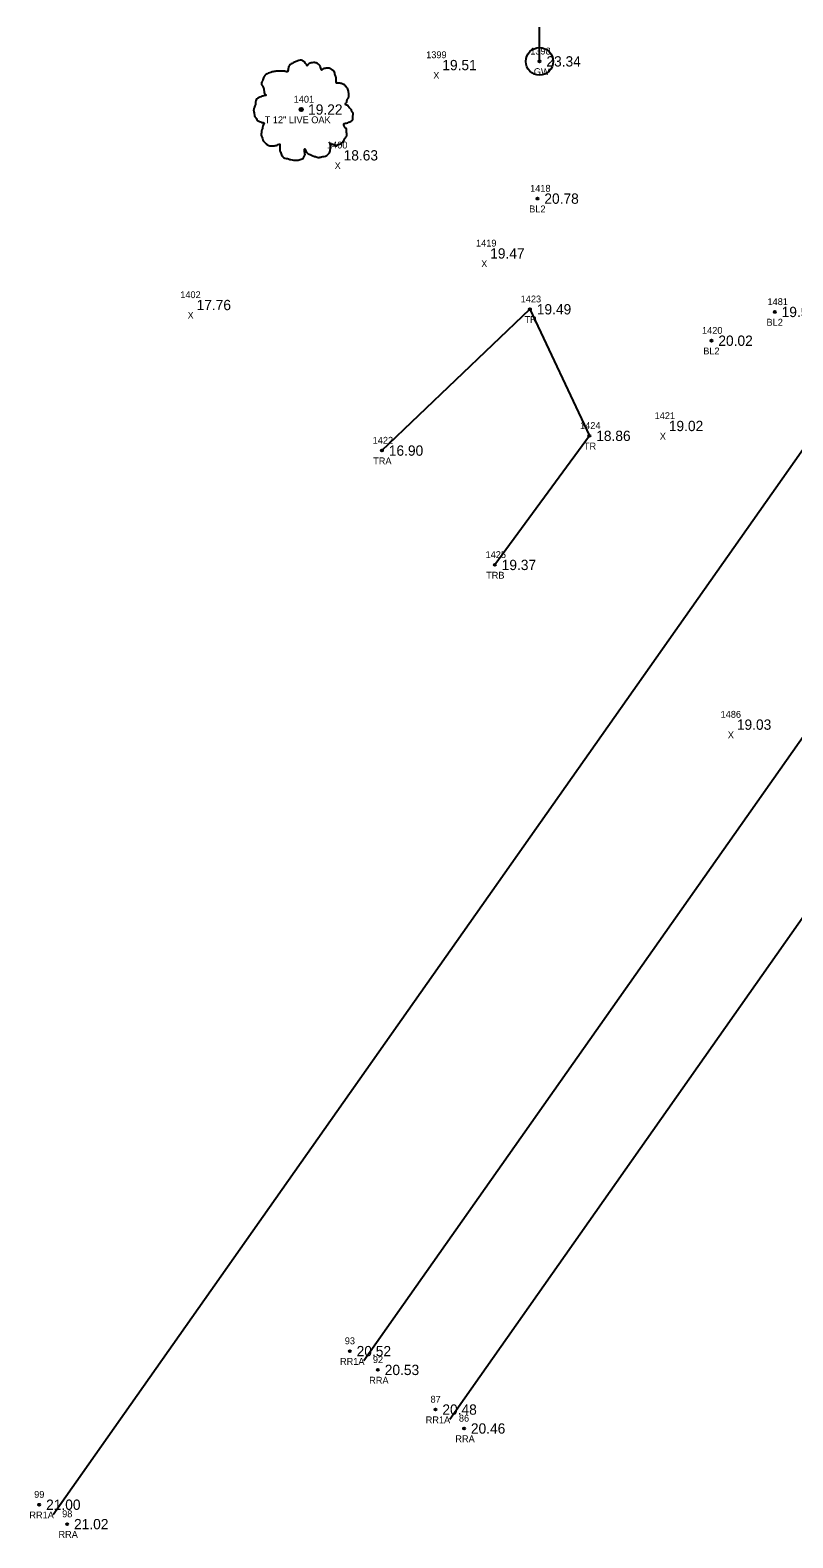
# Model space of a CAD drawing. Extents: x 2042117 to 2045853, y 303080 to 309569.
# Drawn here: x 2043315.7 to 2043426.9, y 305685 to 305904.8 of the extents above; entities that cross this region are included whole.
import ezdxf

# ---------------------------------------------------------------- set-up
doc = ezdxf.new("R2010")
doc.units = 0
for name, color, linetype in [('RD_DTM_BkLn_txCode', 7, 'Continuous'), ('RD_EX_Misc_txCode', 7, 'Continuous'), ('RD_EX_RailRoad', 7, 'Continuous'), ('RD_EX_RailRoad_txCode', 7, 'Continuous'), ('RD_EX_TX_Misc_ELEV', 7, 'Continuous'), ('RD_EX_TX_RailRoad_ELEV', 7, 'Continuous'), ('RD_EX_TX_UT_ELEV', 7, 'Continuous'), ('RD_EX_TX_VEG_ELEV', 7, 'Continuous'), ('RD_EX_UT', 7, 'Continuous'), ('RD_EX_UT_txCode', 7, 'Continuous'), ('RD_EX_VEG', 7, 'Continuous'), ('RD_EX_VEG_txCode', 7, 'Continuous'), ('RD_SMD_Locator', 7, 'Continuous')]:
    doc.layers.add(name, color=color, linetype=linetype)

msp = doc.modelspace()

# ---------------------------------------------------------------- linework, layer by layer
at = {"layer": 'RD_EX_RailRoad'}
for points in [[(2043319.01, 305688.39), (2043467.58, 305899.4), (2043576.81, 306054.41)], [(2043364.31, 305710.83), (2043487.58, 305885.88), (2043596.31, 306040.36)], [(2043376.84, 305702.3), (2043499.95, 305877.29), (2043608.72, 306031.56)]]:
    msp.add_lwpolyline(points, dxfattribs=at)
at = {"layer": 'RD_EX_UT'}
msp.add_line((2043389.93, 305900.22), (2043389.93, 305905.22), dxfattribs=at)
msp.add_circle((2043389.93, 305900.22), 2, dxfattribs=at)
at = {"layer": 'RD_EX_VEG'}
msp.add_lwpolyline([(2043366.95, 305843.48), (2043388.53, 305864.08), (2043397.19, 305845.63), (2043383.41, 305826.81)], dxfattribs=at)
for centre, radius in [((2043355.18, 305893.2), 0.25), ((2043355.17, 305893.18), 0.0001)]:
    msp.add_circle(centre, radius, dxfattribs=at)
for points in [[(2043355.32, 305900.36), (2043355.02, 305900.39), (2043354.69, 305900.29), (2043354.44, 305900.19), (2043354.22, 305900.11), (2043353.99, 305900.01), (2043353.69, 305899.84), (2043353.47, 305899.64), (2043353.34, 305899.39), (2043353.29, 305899.16), (2043353.24, 305898.89), (2043353.24, 305898.72), (2043353.12, 305898.69), (2043352.97, 305898.72), (2043352.72, 305898.79), (2043352.47, 305898.79), (2043352.22, 305898.79), (2043351.87, 305898.77), (2043351.52, 305898.77), (2043351.24, 305898.72), (2043350.92, 305898.67), (2043350.54, 305898.54), (2043350.19, 305898.42), (2043349.89, 305898.17), (2043349.64, 305897.69), (2043349.52, 305897.34), (2043349.37, 305897.09), (2043349.52, 305896.64), (2043349.69, 305896.29), (2043349.72, 305896.09), (2043349.79, 305895.67), (2043349.89, 305895.44), (2043350.02, 305895.24), (2043349.94, 305895.22), (2043349.57, 305895.17), (2043349.27, 305895.07), (2043348.84, 305894.84), (2043348.62, 305894.62), (2043348.52, 305894.29), (2043348.49, 305893.94), (2043348.39, 305893.74), (2043348.32, 305893.47), (2043348.29, 305893.39), (2043348.24, 305893.07), (2043348.34, 305892.62), (2043348.37, 305892.27), (2043348.49, 305892.04), (2043348.64, 305891.87), (2043348.82, 305891.62), (2043349.22, 305891.39), (2043349.54, 305891.29), (2043349.74, 305891.27), (2043349.57, 305890.77), (2043349.52, 305890.42), (2043349.39, 305890.02), (2043349.39, 305889.94), (2043349.34, 305889.47), (2043349.49, 305889.14), (2043349.57, 305888.77), (2043349.74, 305888.54), (2043350.02, 305888.24), (2043350.34, 305888.02), (2043350.84, 305887.89), (2043351.24, 305887.92), (2043351.82, 305888.09), (2043352.07, 305888.17), (2043352.04, 305887.99), (2043352.07, 305887.62), (2043352.07, 305887.2), (2043352.22, 305886.87), (2043352.32, 305886.6), (2043352.47, 305886.35), (2043352.79, 305886.12), (2043353.19, 305886.05), (2043353.62, 305885.9), (2043354.07, 305885.82), (2043354.57, 305885.8), (2043355.17, 305885.95), (2043355.44, 305886.07), (2043355.54, 305886.25), (2043355.74, 305886.62), (2043355.69, 305886.85), (2043355.72, 305887.45), (2043355.82, 305887.27), (2043355.99, 305886.92), (2043356.49, 305886.62), (2043356.89, 305886.45), (2043357.36, 305886.3), (2043357.66, 305886.22), (2043358.14, 305886.3), (2043358.51, 305886.37), (2043358.89, 305886.5), (2043359.19, 305886.77), (2043359.36, 305887.05), (2043359.41, 305887.32), (2043359.49, 305887.69), (2043359.54, 305887.87)], [(2043359.54, 305887.87), (2043359.46, 305888.04), (2043359.41, 305888.29), (2043359.49, 305888.27), (2043359.66, 305888.22), (2043359.94, 305888.09), (2043360.16, 305888.02), (2043360.49, 305888.04), (2043360.76, 305888.14), (2043361.21, 305888.42), (2043361.49, 305888.89), (2043361.76, 305889.29), (2043361.84, 305889.62), (2043361.79, 305889.84), (2043361.76, 305890.34), (2043361.56, 305890.59), (2043361.51, 305890.72), (2043361.41, 305891.12), (2043361.49, 305891.17), (2043361.76, 305891.22), (2043362.14, 305891.34), (2043362.41, 305891.47), (2043362.64, 305891.64), (2043362.71, 305891.87), (2043362.69, 305892.27), (2043362.74, 305892.67), (2043362.66, 305892.82), (2043362.56, 305892.97), (2043362.49, 305893.17), (2043362.34, 305893.32), (2043362.24, 305893.47), (2043362.14, 305893.57), (2043362.01, 305893.72), (2043361.84, 305893.84), (2043361.69, 305893.89), (2043361.64, 305894.04), (2043361.79, 305894.24), (2043361.84, 305894.34), (2043361.86, 305894.57), (2043362.09, 305894.92), (2043362.14, 305895.32), (2043362.09, 305895.74), (2043362.04, 305896.02), (2043361.89, 305896.29), (2043361.69, 305896.54), (2043361.56, 305896.72), (2043361.39, 305896.84), (2043361.06, 305896.97), (2043360.81, 305897.02), (2043360.46, 305897.02), (2043360.26, 305897.07), (2043360.29, 305897.12), (2043360.29, 305897.27), (2043360.29, 305897.54), (2043360.21, 305897.99), (2043360.06, 305898.49), (2043360.06, 305898.52), (2043359.96, 305898.77), (2043359.74, 305898.96), (2043359.56, 305899.06), (2043359.36, 305899.19), (2043359.11, 305899.21), (2043358.81, 305899.21), (2043358.54, 305899.16), (2043358.34, 305899.06), (2043358.16, 305898.94), (2043358.09, 305899.09), (2043357.99, 305899.39), (2043357.94, 305899.54), (2043357.79, 305899.71), (2043357.56, 305899.91), (2043357.11, 305900.04), (2043356.49, 305899.96), (2043356.19, 305899.76), (2043356.04, 305899.59), (2043355.99, 305899.71), (2043355.79, 305899.91), (2043355.69, 305900.09), (2043355.52, 305900.21), (2043355.37, 305900.31), (2043355.27, 305900.36)]]:
    msp.add_spline(points, degree=3, dxfattribs=at)
at = {"layer": 'RD_SMD_Locator'}
for centre in [(2043389.93, 305900.22), (2043355.18, 305893.2), (2043389.63, 305880.21), (2043388.53, 305864.08), (2043424.23, 305863.69), (2043415, 305859.5), (2043397.19, 305845.63), (2043366.95, 305843.48), (2043383.41, 305826.81), (2043362.26, 305712.2), (2043366.36, 305709.46), (2043374.76, 305703.68), (2043378.92, 305700.92), (2043316.98, 305689.81), (2043321.05, 305686.98)]:
    msp.add_circle(centre, 0.15, dxfattribs=at)

# ---------------------------------------------------------------- texts
at = {"layer": 'RD_DTM_BkLn_txCode'}
for s, p in [('1418', (2043388.56, 305881.21)), ('BL2', (2043388.42, 305878.21)), ('1481', (2043423.17, 305864.69)), ('1420', (2043413.62, 305860.5)), ('BL2', (2043423.03, 305861.69)), ('BL2', (2043413.8, 305857.5))]:
    msp.add_text(s, height=1, dxfattribs=at).set_placement(p)
at = {"layer": 'RD_EX_Misc_txCode'}
for s, p in [('1399', (2043373.4, 305900.68)), ('X', (2043374.43, 305897.68)), ('1400', (2043358.94, 305887.52)), ('X', (2043360.05, 305884.52)), ('1419', (2043380.67, 305873.22)), ('X', (2043381.42, 305870.22)), ('1402', (2043337.54, 305865.7)), ('X', (2043338.61, 305862.7)), ('1421', (2043406.71, 305848.07)), ('X', (2043407.46, 305845.07)), ('1486', (2043416.33, 305804.53)), ('X', (2043417.38, 305801.53))]:
    msp.add_text(s, height=1, dxfattribs=at).set_placement(p)
at = {"layer": 'RD_EX_RailRoad_txCode'}
for s, p in [('93', (2043361.53, 305713.2)), ('RR1A', (2043360.83, 305710.2)), ('92', (2043365.63, 305710.46)), ('RRA', (2043365.09, 305707.46)), ('87', (2043374.03, 305704.68)), ('RR1A', (2043373.33, 305701.68)), ('86', (2043378.17, 305701.92)), ('RRA', (2043377.65, 305698.92)), ('99', (2043316.24, 305690.81)), ('RR1A', (2043315.54, 305687.81)), ('98', (2043320.32, 305687.98)), ('RRA', (2043319.78, 305684.98))]:
    msp.add_text(s, height=1, dxfattribs=at).set_placement(p)
at = {"layer": 'RD_EX_TX_Misc_ELEV'}
for s, p in [('19.51', (2043375.75, 305898.93)), ('18.63', (2043361.36, 305885.77)), ('20.78', (2043390.63, 305879.46)), ('19.47', (2043382.73, 305871.47)), ('17.76', (2043339.92, 305863.95)), ('19.55', (2043425.23, 305862.94)), ('20.02', (2043416, 305858.75)), ('19.02', (2043408.78, 305846.32)), ('19.03', (2043418.7, 305802.78))]:
    msp.add_text(s, height=1.5, dxfattribs=at).set_placement(p)
at = {"layer": 'RD_EX_TX_RailRoad_ELEV'}
for s, p in [('20.52', (2043363.26, 305711.45)), ('20.53', (2043367.36, 305708.71)), ('20.48', (2043375.76, 305702.93)), ('20.46', (2043379.92, 305700.17)), ('21.00', (2043317.98, 305689.06)), ('21.02', (2043322.05, 305686.23))]:
    msp.add_text(s, height=1.5, dxfattribs=at).set_placement(p)
at = {"layer": 'RD_EX_TX_UT_ELEV'}
msp.add_text('23.34', height=1.5, dxfattribs=at).set_placement((2043390.93, 305899.47))
at = {"layer": 'RD_EX_TX_VEG_ELEV'}
for s, p in [('19.22', (2043356.18, 305892.45)), ('19.49', (2043389.53, 305863.33)), ('18.86', (2043398.19, 305844.88)), ('16.90', (2043367.95, 305842.73)), ('19.37', (2043384.41, 305826.06))]:
    msp.add_text(s, height=1.5, dxfattribs=at).set_placement(p)
at = {"layer": 'RD_EX_UT_txCode'}
for s, p in [('1398', (2043388.58, 305901.22)), ('GW', (2043389.09, 305898.22))]:
    msp.add_text(s, height=1, dxfattribs=at).set_placement(p)
at = {"layer": 'RD_EX_VEG_txCode'}
for s, p in [('1401', (2043354.08, 305894.2)), ('T 12" LIVE OAK', (2043349.85, 305891.2)), ('1423', (2043387.18, 305865.08)), ('TR', (2043387.73, 305862.08)), ('1424', (2043395.84, 305846.63)), ('1422', (2043365.6, 305844.48)), ('TR', (2043396.4, 305843.63)), ('TRA', (2043365.67, 305841.48)), ('1425', (2043382.06, 305827.81)), ('TRB', (2043382.14, 305824.81))]:
    msp.add_text(s, height=1, dxfattribs=at).set_placement(p)

doc.saveas('drawing.dxf')
